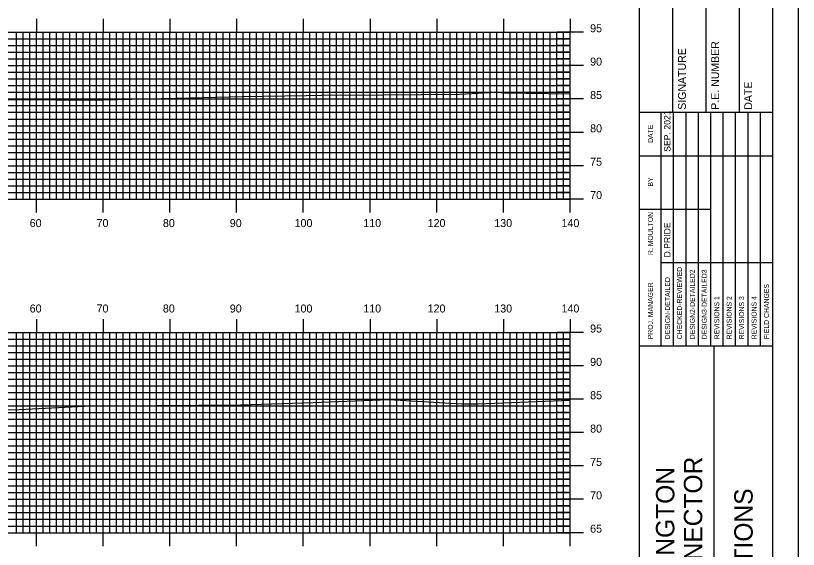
# Model space of a CAD drawing. Extents: x 1777138 to 1777481, y 442591 to 442811.
# Drawn here: x 1777360.6 to 1777478, y 442656.2 to 442736.2 of the extents above; entities that cross this region are included whole.
import ezdxf

# ---------------------------------------------------------------- set-up
doc = ezdxf.new("R2010")
doc.units = 0
for name, color, linetype in [('BORDER', 7, 'Continuous'), ('H_V ANNOTATION', 7, 'Continuous'), ('MAJOR', 7, 'Continuous'), ('MINOR', 7, 'Continuous'), ('PLOT BOUNDARY', 7, 'Continuous'), ('S_Roadway_Centerline', 7, 'Continuous')]:
    doc.layers.add(name, color=color, linetype=linetype)

msp = doc.modelspace()

# ---------------------------------------------------------------- linework, layer by layer
at = {"layer": 'BORDER'}
for p, q in [((1777454.16, 442596.67), (1777454.16, 442806.67)), ((1777459.16, 442721.67), (1777459.16, 442738.97)), ((1777464.16, 442721.67), (1777464.16, 442738.97)), ((1777469.16, 442721.67), (1777469.16, 442738.97)), ((1777454.16, 442721.67), (1777474.16, 442721.67)), ((1777454.16, 442686.67), (1777474.16, 442686.67)), ((1777465.35, 442616.67), (1777465.35, 442686.67))]:
    msp.add_line(p, q, dxfattribs=at)
msp.add_lwpolyline([(1777154.16, 442596.67), (1777474.16, 442596.67), (1777474.16, 442806.67), (1777154.16, 442806.67)], close=True, dxfattribs=at)
for points in [[(1777457.39, 442715.17), (1777457.39, 442721.67)], [(1777459.26, 442686.68), (1777459.26, 442721.67)], [(1777461.12, 442721.67), (1777461.12, 442686.68)], [(1777462.99, 442686.68), (1777462.99, 442721.67)], [(1777464.85, 442686.68), (1777464.85, 442721.67)], [(1777466.71, 442686.68), (1777466.71, 442721.67)], [(1777468.58, 442686.68), (1777468.58, 442721.67)], [(1777470.44, 442686.68), (1777470.44, 442721.67)], [(1777472.3, 442686.68), (1777472.3, 442721.67)], [(1777457.4, 442686.68), (1777457.4, 442720.26)], [(1777454.16, 442715.17), (1777474.16, 442715.17)], [(1777454.16, 442707.17), (1777457.4, 442707.17)], [(1777457.39, 442707.17), (1777464.85, 442707.17)], [(1777457.39, 442699.17), (1777474.16, 442699.17)]]:
    msp.add_lwpolyline(points, dxfattribs=at)
at = {"layer": 'MAJOR'}
for p, q in [((1777363.76, 442735.67), (1777363.76, 442733.67)), ((1777373.76, 442735.67), (1777373.76, 442733.67)), ((1777383.76, 442735.67), (1777383.76, 442733.67)), ((1777393.76, 442735.67), (1777393.76, 442733.67)), ((1777403.76, 442735.67), (1777403.76, 442733.67)), ((1777413.76, 442735.67), (1777413.76, 442733.67)), ((1777423.76, 442735.67), (1777423.76, 442733.67)), ((1777433.76, 442735.67), (1777433.76, 442733.67)), ((1777443.76, 442735.67), (1777443.76, 442733.67)), ((1777163.76, 442733.67), (1777443.76, 442733.67)), ((1777163.76, 442733.67), (1777443.76, 442733.67)), ((1777363.76, 442708.67), (1777363.76, 442733.67)), ((1777373.76, 442708.67), (1777373.76, 442733.67)), ((1777383.76, 442708.67), (1777383.76, 442733.67)), ((1777393.76, 442708.67), (1777393.76, 442733.67)), ((1777403.76, 442708.67), (1777403.76, 442733.67)), ((1777413.76, 442708.67), (1777413.76, 442733.67)), ((1777423.76, 442708.67), (1777423.76, 442733.67)), ((1777433.76, 442708.67), (1777433.76, 442733.67)), ((1777445.77, 442733.67), (1777441.76, 442733.67)), ((1777443.76, 442708.67), (1777443.76, 442733.67)), ((1777443.76, 442708.67), (1777443.76, 442733.67)), ((1777163.76, 442728.67), (1777443.76, 442728.67)), ((1777445.77, 442728.67), (1777441.76, 442728.67)), ((1777163.76, 442723.67), (1777443.76, 442723.67)), ((1777445.77, 442723.67), (1777441.76, 442723.67)), ((1777163.76, 442718.67), (1777443.76, 442718.67)), ((1777445.77, 442718.67), (1777441.76, 442718.67)), ((1777163.76, 442713.67), (1777443.76, 442713.67)), ((1777445.77, 442713.67), (1777441.76, 442713.67)), ((1777163.76, 442708.67), (1777443.76, 442708.67)), ((1777163.76, 442708.67), (1777443.76, 442708.67)), ((1777363.76, 442706.66), (1777363.76, 442708.67)), ((1777373.76, 442706.66), (1777373.76, 442708.67)), ((1777383.76, 442706.66), (1777383.76, 442708.67)), ((1777393.76, 442706.66), (1777393.76, 442708.67)), ((1777403.76, 442706.66), (1777403.76, 442708.67)), ((1777413.76, 442706.66), (1777413.76, 442708.67)), ((1777423.76, 442706.66), (1777423.76, 442708.67)), ((1777433.76, 442706.66), (1777433.76, 442708.67)), ((1777445.77, 442708.67), (1777441.76, 442708.67)), ((1777443.76, 442706.66), (1777443.76, 442708.67)), ((1777363.76, 442690.67), (1777363.76, 442688.67)), ((1777373.76, 442690.67), (1777373.76, 442688.67)), ((1777383.76, 442690.67), (1777383.76, 442688.67)), ((1777393.76, 442690.67), (1777393.76, 442688.67)), ((1777403.76, 442690.67), (1777403.76, 442688.67)), ((1777413.76, 442690.67), (1777413.76, 442688.67)), ((1777423.76, 442690.67), (1777423.76, 442688.67)), ((1777433.76, 442690.67), (1777433.76, 442688.67)), ((1777443.76, 442690.67), (1777443.76, 442688.67)), ((1777163.76, 442688.67), (1777443.76, 442688.67)), ((1777163.76, 442688.67), (1777443.76, 442688.67)), ((1777363.76, 442658.67), (1777363.76, 442688.67)), ((1777373.76, 442658.67), (1777373.76, 442688.67)), ((1777383.76, 442658.67), (1777383.76, 442688.67)), ((1777393.76, 442658.67), (1777393.76, 442688.67)), ((1777403.76, 442658.67), (1777403.76, 442688.67)), ((1777413.76, 442658.67), (1777413.76, 442688.67)), ((1777423.76, 442658.67), (1777423.76, 442688.67)), ((1777433.76, 442658.67), (1777433.76, 442688.67)), ((1777445.77, 442688.67), (1777441.76, 442688.67)), ((1777443.76, 442658.67), (1777443.76, 442688.67)), ((1777443.76, 442658.67), (1777443.76, 442688.67)), ((1777163.76, 442683.67), (1777443.76, 442683.67)), ((1777445.77, 442683.67), (1777441.76, 442683.67)), ((1777163.76, 442678.67), (1777443.76, 442678.67)), ((1777445.77, 442678.67), (1777441.76, 442678.67)), ((1777163.76, 442673.67), (1777443.76, 442673.67)), ((1777445.77, 442673.67), (1777441.76, 442673.67)), ((1777163.76, 442668.67), (1777443.76, 442668.67)), ((1777445.77, 442668.67), (1777441.76, 442668.67)), ((1777163.76, 442663.67), (1777443.76, 442663.67)), ((1777445.77, 442663.67), (1777441.76, 442663.67)), ((1777163.76, 442658.67), (1777443.76, 442658.67)), ((1777163.76, 442658.67), (1777443.76, 442658.67)), ((1777363.76, 442656.66), (1777363.76, 442658.67)), ((1777373.76, 442656.66), (1777373.76, 442658.67)), ((1777383.76, 442656.66), (1777383.76, 442658.67)), ((1777393.76, 442656.66), (1777393.76, 442658.67)), ((1777403.76, 442656.66), (1777403.76, 442658.67)), ((1777413.76, 442656.66), (1777413.76, 442658.67)), ((1777423.76, 442656.66), (1777423.76, 442658.67)), ((1777433.76, 442656.66), (1777433.76, 442658.67)), ((1777445.77, 442658.67), (1777441.76, 442658.67)), ((1777443.76, 442656.66), (1777443.76, 442658.67))]:
    msp.add_line(p, q, dxfattribs=at)
at = {"layer": 'MINOR'}
for p, q in [((1777163.76, 442732.67), (1777443.76, 442732.67)), ((1777360.76, 442708.67), (1777360.76, 442733.67)), ((1777361.76, 442708.67), (1777361.76, 442733.67)), ((1777362.76, 442708.67), (1777362.76, 442733.67)), ((1777364.76, 442708.67), (1777364.76, 442733.67)), ((1777365.76, 442708.67), (1777365.76, 442733.67)), ((1777366.76, 442708.67), (1777366.76, 442733.67)), ((1777367.76, 442708.67), (1777367.76, 442733.67)), ((1777368.76, 442708.67), (1777368.76, 442733.67)), ((1777369.76, 442708.67), (1777369.76, 442733.67)), ((1777370.76, 442708.67), (1777370.76, 442733.67)), ((1777371.76, 442708.67), (1777371.76, 442733.67)), ((1777372.76, 442708.67), (1777372.76, 442733.67)), ((1777374.76, 442708.67), (1777374.76, 442733.67)), ((1777375.76, 442708.67), (1777375.76, 442733.67)), ((1777376.76, 442708.67), (1777376.76, 442733.67)), ((1777377.76, 442708.67), (1777377.76, 442733.67)), ((1777378.76, 442708.67), (1777378.76, 442733.67)), ((1777379.76, 442708.67), (1777379.76, 442733.67)), ((1777380.76, 442708.67), (1777380.76, 442733.67)), ((1777381.76, 442708.67), (1777381.76, 442733.67)), ((1777382.76, 442708.67), (1777382.76, 442733.67)), ((1777384.76, 442708.67), (1777384.76, 442733.67)), ((1777385.76, 442708.67), (1777385.76, 442733.67)), ((1777386.76, 442708.67), (1777386.76, 442733.67)), ((1777387.76, 442708.67), (1777387.76, 442733.67)), ((1777388.76, 442708.67), (1777388.76, 442733.67)), ((1777389.76, 442708.67), (1777389.76, 442733.67)), ((1777390.76, 442708.67), (1777390.76, 442733.67)), ((1777391.76, 442708.67), (1777391.76, 442733.67)), ((1777392.76, 442708.67), (1777392.76, 442733.67)), ((1777394.76, 442708.67), (1777394.76, 442733.67)), ((1777395.76, 442708.67), (1777395.76, 442733.67)), ((1777396.76, 442708.67), (1777396.76, 442733.67)), ((1777397.76, 442708.67), (1777397.76, 442733.67)), ((1777398.76, 442708.67), (1777398.76, 442733.67)), ((1777399.76, 442708.67), (1777399.76, 442733.67)), ((1777400.76, 442708.67), (1777400.76, 442733.67)), ((1777401.76, 442708.67), (1777401.76, 442733.67)), ((1777402.76, 442708.67), (1777402.76, 442733.67)), ((1777404.76, 442708.67), (1777404.76, 442733.67)), ((1777405.76, 442708.67), (1777405.76, 442733.67)), ((1777406.76, 442708.67), (1777406.76, 442733.67)), ((1777407.76, 442708.67), (1777407.76, 442733.67)), ((1777408.76, 442708.67), (1777408.76, 442733.67)), ((1777409.76, 442708.67), (1777409.76, 442733.67)), ((1777410.76, 442708.67), (1777410.76, 442733.67)), ((1777411.76, 442708.67), (1777411.76, 442733.67)), ((1777412.76, 442708.67), (1777412.76, 442733.67)), ((1777414.76, 442708.67), (1777414.76, 442733.67)), ((1777415.76, 442708.67), (1777415.76, 442733.67)), ((1777416.76, 442708.67), (1777416.76, 442733.67)), ((1777417.76, 442708.67), (1777417.76, 442733.67)), ((1777418.76, 442708.67), (1777418.76, 442733.67)), ((1777419.76, 442708.67), (1777419.76, 442733.67)), ((1777420.76, 442708.67), (1777420.76, 442733.67)), ((1777421.76, 442708.67), (1777421.76, 442733.67)), ((1777422.76, 442708.67), (1777422.76, 442733.67)), ((1777424.76, 442708.67), (1777424.76, 442733.67)), ((1777425.76, 442708.67), (1777425.76, 442733.67)), ((1777426.76, 442708.67), (1777426.76, 442733.67)), ((1777427.76, 442708.67), (1777427.76, 442733.67)), ((1777428.76, 442708.67), (1777428.76, 442733.67)), ((1777429.76, 442708.67), (1777429.76, 442733.67)), ((1777430.76, 442708.67), (1777430.76, 442733.67)), ((1777431.76, 442708.67), (1777431.76, 442733.67)), ((1777432.76, 442708.67), (1777432.76, 442733.67)), ((1777434.76, 442708.67), (1777434.76, 442733.67)), ((1777435.76, 442708.67), (1777435.76, 442733.67)), ((1777436.76, 442708.67), (1777436.76, 442733.67)), ((1777437.76, 442708.67), (1777437.76, 442733.67)), ((1777438.76, 442708.67), (1777438.76, 442733.67)), ((1777439.76, 442708.67), (1777439.76, 442733.67)), ((1777440.76, 442708.67), (1777440.76, 442733.67)), ((1777441.76, 442708.67), (1777441.76, 442733.67)), ((1777443.76, 442732.67), (1777441.76, 442732.67)), ((1777442.76, 442708.67), (1777442.76, 442733.67)), ((1777163.76, 442731.67), (1777443.76, 442731.67)), ((1777443.76, 442731.67), (1777441.76, 442731.67)), ((1777163.76, 442730.67), (1777443.76, 442730.67)), ((1777443.76, 442730.67), (1777441.76, 442730.67)), ((1777163.76, 442729.67), (1777443.76, 442729.67)), ((1777443.76, 442729.67), (1777441.76, 442729.67)), ((1777163.76, 442727.67), (1777443.76, 442727.67)), ((1777163.76, 442726.67), (1777443.76, 442726.67)), ((1777443.76, 442727.67), (1777441.76, 442727.67)), ((1777443.76, 442726.67), (1777441.76, 442726.67)), ((1777163.76, 442725.67), (1777443.76, 442725.67)), ((1777443.76, 442725.67), (1777441.76, 442725.67)), ((1777163.76, 442724.67), (1777443.76, 442724.67)), ((1777443.76, 442724.67), (1777441.76, 442724.67)), ((1777163.76, 442722.67), (1777443.76, 442722.67)), ((1777443.76, 442722.67), (1777441.76, 442722.67)), ((1777163.76, 442721.67), (1777443.76, 442721.67)), ((1777443.76, 442721.67), (1777441.76, 442721.67)), ((1777163.76, 442720.67), (1777443.76, 442720.67)), ((1777163.76, 442719.67), (1777443.76, 442719.67)), ((1777443.76, 442720.67), (1777441.76, 442720.67)), ((1777443.76, 442719.67), (1777441.76, 442719.67)), ((1777163.76, 442717.67), (1777443.76, 442717.67)), ((1777443.76, 442717.67), (1777441.76, 442717.67)), ((1777163.76, 442716.67), (1777443.76, 442716.67)), ((1777443.76, 442716.67), (1777441.76, 442716.67)), ((1777163.76, 442715.67), (1777443.76, 442715.67)), ((1777443.76, 442715.67), (1777441.76, 442715.67)), ((1777163.76, 442714.67), (1777443.76, 442714.67)), ((1777443.76, 442714.67), (1777441.76, 442714.67)), ((1777163.76, 442712.67), (1777443.76, 442712.67)), ((1777443.76, 442712.67), (1777441.76, 442712.67)), ((1777163.76, 442711.67), (1777443.76, 442711.67)), ((1777443.76, 442711.67), (1777441.76, 442711.67)), ((1777163.76, 442710.67), (1777443.76, 442710.67)), ((1777443.76, 442710.67), (1777441.76, 442710.67)), ((1777163.76, 442709.67), (1777443.76, 442709.67)), ((1777443.76, 442709.67), (1777441.76, 442709.67)), ((1777360.76, 442658.67), (1777360.76, 442688.67)), ((1777361.76, 442658.67), (1777361.76, 442688.67)), ((1777362.76, 442658.67), (1777362.76, 442688.67)), ((1777364.76, 442658.67), (1777364.76, 442688.67)), ((1777365.76, 442658.67), (1777365.76, 442688.67)), ((1777366.76, 442658.67), (1777366.76, 442688.67)), ((1777367.76, 442658.67), (1777367.76, 442688.67)), ((1777368.76, 442658.67), (1777368.76, 442688.67)), ((1777369.76, 442658.67), (1777369.76, 442688.67)), ((1777370.76, 442658.67), (1777370.76, 442688.67)), ((1777371.76, 442658.67), (1777371.76, 442688.67)), ((1777372.76, 442658.67), (1777372.76, 442688.67)), ((1777374.76, 442658.67), (1777374.76, 442688.67)), ((1777375.76, 442658.67), (1777375.76, 442688.67)), ((1777376.76, 442658.67), (1777376.76, 442688.67)), ((1777377.76, 442658.67), (1777377.76, 442688.67)), ((1777378.76, 442658.67), (1777378.76, 442688.67)), ((1777379.76, 442658.67), (1777379.76, 442688.67)), ((1777380.76, 442658.67), (1777380.76, 442688.67)), ((1777381.76, 442658.67), (1777381.76, 442688.67)), ((1777382.76, 442658.67), (1777382.76, 442688.67)), ((1777384.76, 442658.67), (1777384.76, 442688.67)), ((1777385.76, 442658.67), (1777385.76, 442688.67)), ((1777386.76, 442658.67), (1777386.76, 442688.67)), ((1777387.76, 442658.67), (1777387.76, 442688.67)), ((1777388.76, 442658.67), (1777388.76, 442688.67)), ((1777389.76, 442658.67), (1777389.76, 442688.67)), ((1777390.76, 442658.67), (1777390.76, 442688.67)), ((1777391.76, 442658.67), (1777391.76, 442688.67)), ((1777392.76, 442658.67), (1777392.76, 442688.67)), ((1777394.76, 442658.67), (1777394.76, 442688.67)), ((1777395.76, 442658.67), (1777395.76, 442688.67)), ((1777396.76, 442658.67), (1777396.76, 442688.67)), ((1777397.76, 442658.67), (1777397.76, 442688.67)), ((1777398.76, 442658.67), (1777398.76, 442688.67)), ((1777399.76, 442658.67), (1777399.76, 442688.67)), ((1777400.76, 442658.67), (1777400.76, 442688.67)), ((1777401.76, 442658.67), (1777401.76, 442688.67)), ((1777402.76, 442658.67), (1777402.76, 442688.67)), ((1777404.76, 442658.67), (1777404.76, 442688.67)), ((1777405.76, 442658.67), (1777405.76, 442688.67)), ((1777406.76, 442658.67), (1777406.76, 442688.67)), ((1777407.76, 442658.67), (1777407.76, 442688.67)), ((1777408.76, 442658.67), (1777408.76, 442688.67)), ((1777409.76, 442658.67), (1777409.76, 442688.67)), ((1777410.76, 442658.67), (1777410.76, 442688.67)), ((1777411.76, 442658.67), (1777411.76, 442688.67)), ((1777412.76, 442658.67), (1777412.76, 442688.67)), ((1777414.76, 442658.67), (1777414.76, 442688.67)), ((1777415.76, 442658.67), (1777415.76, 442688.67)), ((1777416.76, 442658.67), (1777416.76, 442688.67)), ((1777417.76, 442658.67), (1777417.76, 442688.67)), ((1777418.76, 442658.67), (1777418.76, 442688.67)), ((1777419.76, 442658.67), (1777419.76, 442688.67)), ((1777420.76, 442658.67), (1777420.76, 442688.67)), ((1777421.76, 442658.67), (1777421.76, 442688.67)), ((1777422.76, 442658.67), (1777422.76, 442688.67)), ((1777424.76, 442658.67), (1777424.76, 442688.67)), ((1777425.76, 442658.67), (1777425.76, 442688.67)), ((1777426.76, 442658.67), (1777426.76, 442688.67)), ((1777427.76, 442658.67), (1777427.76, 442688.67)), ((1777428.76, 442658.67), (1777428.76, 442688.67)), ((1777429.76, 442658.67), (1777429.76, 442688.67)), ((1777430.76, 442658.67), (1777430.76, 442688.67)), ((1777431.76, 442658.67), (1777431.76, 442688.67)), ((1777432.76, 442658.67), (1777432.76, 442688.67)), ((1777434.76, 442658.67), (1777434.76, 442688.67)), ((1777435.76, 442658.67), (1777435.76, 442688.67)), ((1777436.76, 442658.67), (1777436.76, 442688.67)), ((1777437.76, 442658.67), (1777437.76, 442688.67)), ((1777438.76, 442658.67), (1777438.76, 442688.67)), ((1777439.76, 442658.67), (1777439.76, 442688.67)), ((1777440.76, 442658.67), (1777440.76, 442688.67)), ((1777441.76, 442658.67), (1777441.76, 442688.67)), ((1777442.76, 442658.67), (1777442.76, 442688.67)), ((1777163.76, 442687.67), (1777443.76, 442687.67)), ((1777443.76, 442687.67), (1777441.76, 442687.67)), ((1777163.76, 442686.67), (1777443.76, 442686.67)), ((1777163.76, 442685.67), (1777443.76, 442685.67)), ((1777443.76, 442686.67), (1777441.76, 442686.67)), ((1777443.76, 442685.67), (1777441.76, 442685.67)), ((1777163.76, 442684.67), (1777443.76, 442684.67)), ((1777443.76, 442684.67), (1777441.76, 442684.67)), ((1777163.76, 442682.67), (1777443.76, 442682.67)), ((1777443.76, 442682.67), (1777441.76, 442682.67)), ((1777163.76, 442681.67), (1777443.76, 442681.67)), ((1777443.76, 442681.67), (1777441.76, 442681.67)), ((1777163.76, 442680.67), (1777443.76, 442680.67)), ((1777443.76, 442680.67), (1777441.76, 442680.67)), ((1777163.76, 442679.67), (1777443.76, 442679.67)), ((1777443.76, 442679.67), (1777441.76, 442679.67)), ((1777163.76, 442677.67), (1777443.76, 442677.67)), ((1777443.76, 442677.67), (1777441.76, 442677.67)), ((1777163.76, 442676.67), (1777443.76, 442676.67)), ((1777443.76, 442676.67), (1777441.76, 442676.67)), ((1777163.76, 442675.67), (1777443.76, 442675.67)), ((1777443.76, 442675.67), (1777441.76, 442675.67)), ((1777163.76, 442674.67), (1777443.76, 442674.67)), ((1777443.76, 442674.67), (1777441.76, 442674.67)), ((1777163.76, 442672.67), (1777443.76, 442672.67)), ((1777163.76, 442671.67), (1777443.76, 442671.67)), ((1777443.76, 442672.67), (1777441.76, 442672.67)), ((1777443.76, 442671.67), (1777441.76, 442671.67)), ((1777163.76, 442670.67), (1777443.76, 442670.67)), ((1777443.76, 442670.67), (1777441.76, 442670.67)), ((1777163.76, 442669.67), (1777443.76, 442669.67)), ((1777443.76, 442669.67), (1777441.76, 442669.67)), ((1777163.76, 442667.67), (1777443.76, 442667.67)), ((1777443.76, 442667.67), (1777441.76, 442667.67)), ((1777163.76, 442666.67), (1777443.76, 442666.67)), ((1777163.76, 442665.67), (1777443.76, 442665.67)), ((1777443.76, 442666.67), (1777441.76, 442666.67)), ((1777443.76, 442665.67), (1777441.76, 442665.67)), ((1777163.76, 442664.67), (1777443.76, 442664.67)), ((1777443.76, 442664.67), (1777441.76, 442664.67)), ((1777163.76, 442662.67), (1777443.76, 442662.67)), ((1777443.76, 442662.67), (1777441.76, 442662.67)), ((1777163.76, 442661.67), (1777443.76, 442661.67)), ((1777443.76, 442661.67), (1777441.76, 442661.67)), ((1777163.76, 442660.67), (1777443.76, 442660.67)), ((1777443.76, 442660.67), (1777441.76, 442660.67)), ((1777163.76, 442659.67), (1777443.76, 442659.67)), ((1777443.76, 442659.67), (1777441.76, 442659.67))]:
    msp.add_line(p, q, dxfattribs=at)
at = {"layer": 'PLOT BOUNDARY'}
msp.add_lwpolyline([(1777137.98, 442590.55), (1777477.98, 442590.55), (1777477.98, 442810.55), (1777137.98, 442810.55)], close=True, dxfattribs=at)
at = {"layer": 'S_Roadway_Centerline'}
for points in [[(1777359.02, 442723.53), (1777361.9, 442723.61), (1777371.52, 442723.48), (1777384.63, 442723.78), (1777394.59, 442724.05), (1777404.2, 442724.19), (1777408.79, 442724.27), (1777410.13, 442724.26), (1777427.17, 442724.41), (1777432.82, 442724.71), (1777433.92, 442724.58), (1777443.76, 442724.45)], [(1777359.33, 442677.09), (1777361.14, 442677.14), (1777370.98, 442677.64), (1777381.87, 442677.75), (1777394.36, 442677.81), (1777405.22, 442678.16), (1777416.59, 442678.62), (1777427.52, 442677.97), (1777429.91, 442677.97), (1777443.76, 442678.53)]]:
    msp.add_lwpolyline(points, dxfattribs=at)

# ---------------------------------------------------------------- texts
at = {"layer": 'BORDER'}
for s, height, p in [('P.E. NUMBER', 1.1811, (1777466.09, 442722.06)), ('SIGNATURE', 1.181, (1777461.12, 442722.06)), ('DATE', 1.181, (1777471.05, 442722.06)), ('SEP. 2021', 0.969, (1777458.81, 442715.76)), ('DATE', 0.743, (1777456.17, 442717.08)), ('BY', 0.743, (1777456.17, 442710.54)), ('R. MOULTON', 0.745, (1777456.17, 442700.28)), ('D.PRIDE', 0.969, (1777458.81, 442699.92)), ('CHECKED-REVIEWED', 0.7455, (1777460.53, 442687.65)), ('DESIGN2-DETAILED2', 0.7455, (1777462.46, 442687.65)), ('DESIGN3-DETAILED3', 0.7455, (1777464.25, 442687.65)), ('DESIGN-DETAILED', 0.7455, (1777458.74, 442687.65)), ('PROJ. MANAGER', 0.7455, (1777456.17, 442687.65)), ('FIELD CHANGES', 0.7455, (1777473.57, 442687.65)), ('REVISIONS 1', 0.7455, (1777466.12, 442687.65)), ('REVISIONS 2', 0.7455, (1777467.98, 442687.65)), ('REVISIONS 3', 0.7455, (1777469.84, 442687.65)), ('REVISIONS 4', 0.7455, (1777471.71, 442687.65)), ('1-395/ROUTE 9 CONNECTOR', 2.7557, (1777463.57, 442618.87)), ('BREWER TO EDDINGTON', 2.7557, (1777459.39, 442623.07)), ('CROSS SECTIONS', 2.7557, (1777471.13, 442632.34))]:
    msp.add_text(s, height=height, rotation=90, dxfattribs=at).set_placement(p)
at = {"layer": 'H_V ANNOTATION'}
for s, p in [('95', (1777446.76, 442733.67)), ('90', (1777446.76, 442728.67)), ('85', (1777446.76, 442723.67)), ('80', (1777446.76, 442718.67)), ('75', (1777446.76, 442713.67)), ('70', (1777446.76, 442708.67)), ('60', (1777362.74, 442704.47)), ('70', (1777372.77, 442704.47)), ('80', (1777382.71, 442704.47)), ('90', (1777392.74, 442704.47)), ('100', (1777402.45, 442704.47)), ('110', (1777412.75, 442704.47)), ('120', (1777422.4, 442704.47)), ('130', (1777432.39, 442704.47)), ('140', (1777442.47, 442704.47)), ('60', (1777362.74, 442691.67)), ('70', (1777372.77, 442691.67)), ('80', (1777382.71, 442691.67)), ('90', (1777392.74, 442691.67)), ('100', (1777402.45, 442691.67)), ('110', (1777412.75, 442691.67)), ('120', (1777422.4, 442691.67)), ('130', (1777432.39, 442691.67)), ('140', (1777442.47, 442691.67)), ('95', (1777446.76, 442688.67)), ('90', (1777446.76, 442683.67)), ('85', (1777446.76, 442678.67)), ('80', (1777446.76, 442673.67)), ('75', (1777446.76, 442668.67)), ('70', (1777446.76, 442663.67)), ('65', (1777446.76, 442658.67))]:
    msp.add_text(s, height=1.2, dxfattribs=at).set_placement(p)

doc.saveas('drawing.dxf')
